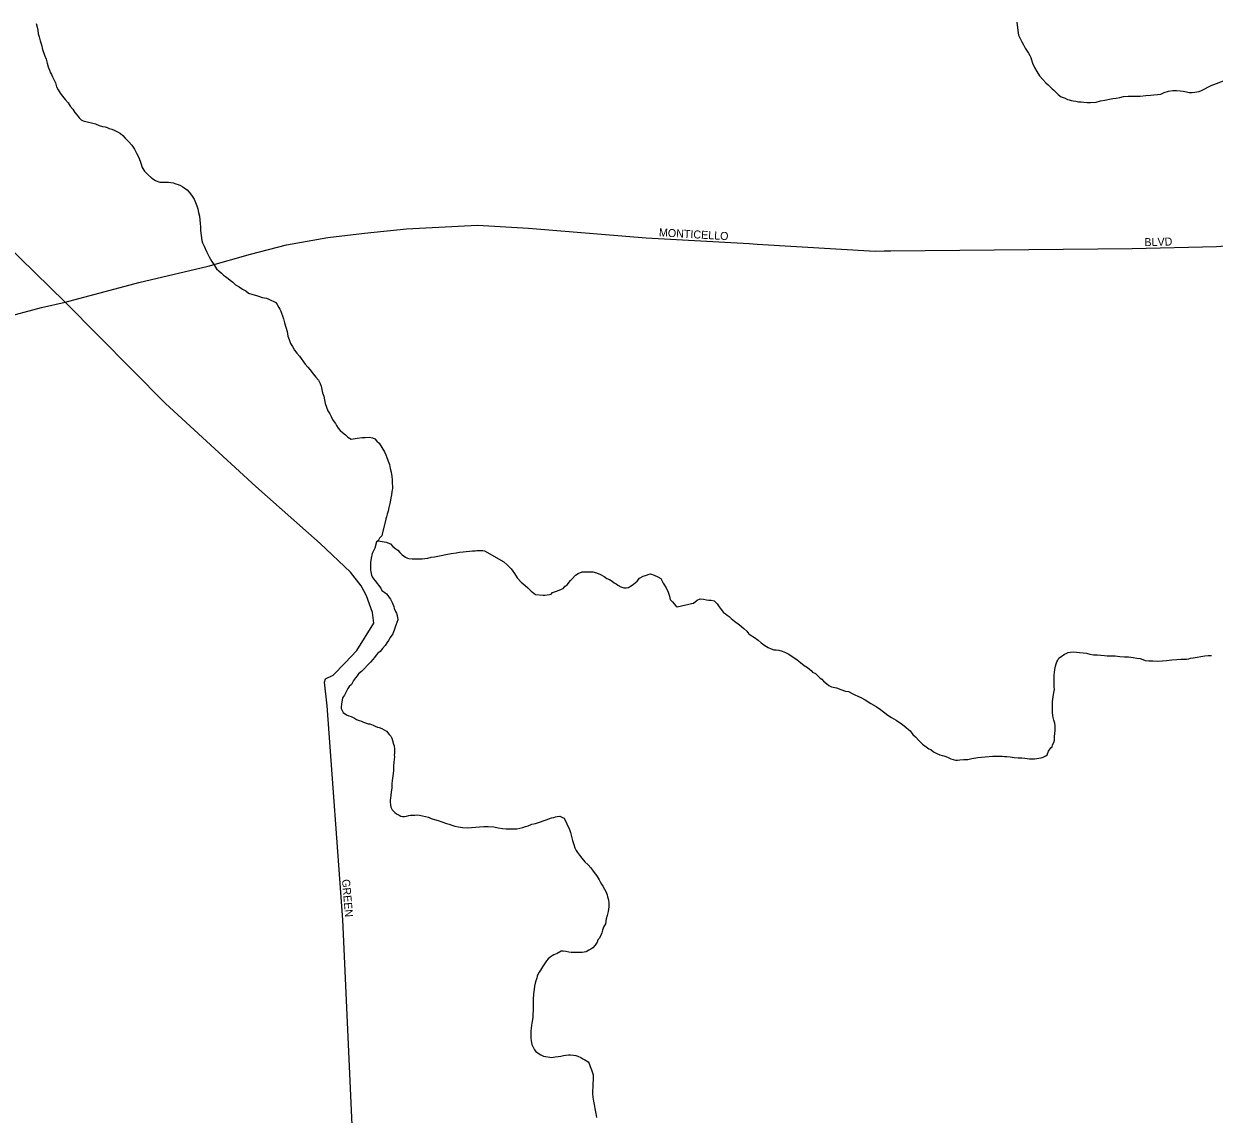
# Model space of a CAD drawing. Extents: x 2139079 to 2262683, y 1235796 to 1334992.
# Drawn here: x 2235020 to 2242458, y 1285350 to 1292167 of the extents above; entities that cross this region are included whole.
import ezdxf

# ---------------------------------------------------------------- set-up
doc = ezdxf.new("R2010")
doc.units = 0
for name, color, linetype in [('GM_X_City_Street', 7, 'Continuous'), ('GM_X_City_Street_Text', 7, 'Continuous'), ('GM_X_Minor_River', 7, 'Continuous')]:
    doc.layers.add(name, color=color, linetype=linetype)

msp = doc.modelspace()

# ---------------------------------------------------------------- linework, layer by layer
at = {"layer": 'GM_X_City_Street'}
for points in [[(2237139.1, 1283818.1), (2237013.6, 1286565.2), (2236914.8, 1287903.6), (2236898.9, 1288051.7), (2236904.4, 1288071.9), (2236952, 1288095.2), (2237028.2, 1288171.5), (2237100.3, 1288249.6), (2237206.3, 1288419), (2237198.5, 1288487), (2237161.7, 1288590.5), (2237128, 1288653.8), (2237061.6, 1288738.4), (2236872.5, 1288918.2), (2236470.3, 1289275.2), (2235905.5, 1289792.5), (2235277.5, 1290426.7), (2232535.6, 1293111.5)], [(2235277.5, 1290426.7), (2235737.5, 1290549), (2236172, 1290652.6), (2236436.7, 1290727.7), (2236661.8, 1290785.7), (2236919.3, 1290830.5), (2237149.2, 1290858.5), (2237411.2, 1290885.4), (2237855.7, 1290908.9), (2238173, 1290889.1), (2238908.5, 1290829.8), (2239552.6, 1290792.5)], [(2239552.6, 1290792.5), (2239603.3, 1290789.5), (2240338.8, 1290746.4), (2240396.7, 1290746.9)], [(2240396.7, 1290746.9), (2240437.6, 1290747.3), (2241946, 1290761.4), (2242473.5, 1290775.7), (2242651.3, 1290787.6), (2242817.4, 1290793.7), (2243007, 1290803.3), (2243195.4, 1290819.4)], [(2233595.7, 1289787), (2233739.2, 1289895.1), (2233988.7, 1290020), (2234081.8, 1290064.5), (2234168.9, 1290104.9), (2234373.1, 1290196.5), (2234636.1, 1290261.6), (2234883.1, 1290326.2), (2235130, 1290392.8), (2235277.5, 1290426.7)]]:
    msp.add_lwpolyline(points, dxfattribs=at)
at = {"layer": 'GM_X_Minor_River'}
for points in [[(2235097.1, 1292168.8), (2235103.6, 1292146.8)], [(2235103.6, 1292146.8), (2235108, 1292126.8), (2235110.4, 1292104.8), (2235114.9, 1292084.8), (2235121.4, 1292060.8), (2235129.9, 1292034.9), (2235136.5, 1292006.8), (2235149.3, 1291970.9), (2235159.8, 1291947), (2235166.4, 1291921.1), (2235172.9, 1291897.1), (2235179.4, 1291877.1), (2235185.7, 1291861.1), (2235192, 1291849.2), (2235198.3, 1291835.3), (2235204.5, 1291823.3), (2235210.8, 1291811.4), (2235217.1, 1291797.5), (2235223.6, 1291773.5), (2235234.1, 1291753.6), (2235246.5, 1291733.8), (2235261, 1291713.9), (2235277.5, 1291694.2), (2235296, 1291672.4), (2235310.4, 1291652.6), (2235326.9, 1291632.8), (2235339.4, 1291613), (2235353.8, 1291595.2), (2235366.2, 1291579.4), (2235378.4, 1291567.5), (2235390.7, 1291559.7), (2235467.3, 1291541.1), (2235491.6, 1291531.6), (2235511.8, 1291525.9), (2235528, 1291522.2), (2235540.1, 1291518.4), (2235552.3, 1291512.6), (2235570.4, 1291509), (2235584.6, 1291501.2), (2235604.9, 1291491.6), (2235623.2, 1291481.9), (2235637.5, 1291468.1), (2235653.9, 1291452.3), (2235674.4, 1291430.6), (2235694.9, 1291408.9), (2235711.5, 1291383.1), (2235724.1, 1291357.3), (2235738.7, 1291331.4), (2235751.5, 1291295.5), (2235760, 1291269.6), (2235774.6, 1291245.7), (2235795.1, 1291224), (2235819.6, 1291202.4), (2235842, 1291186.8), (2235856.2, 1291181), (2235870.3, 1291177.3), (2235898.4, 1291177.8), (2235924.6, 1291176.3), (2235952.8, 1291172.8), (2235969, 1291167.1), (2235985.1, 1291161.4), (2235999.3, 1291155.6), (2236013.5, 1291147.9), (2236029.8, 1291136.1), (2236040, 1291128.3), (2236052.4, 1291114.5), (2236066.8, 1291094.7), (2236083.4, 1291070.9), (2236091.8, 1291048.9), (2236100.3, 1291029), (2236106.7, 1291011.1), (2236111.2, 1290987.1), (2236117.7, 1290965.1), (2236120.2, 1290941), (2236122.6, 1290919), (2236123.1, 1290896.9), (2236123.5, 1290874.8), (2236132.8, 1290812.7), (2236137.1, 1290798.7), (2236141.3, 1290788.8), (2236147.6, 1290776.8), (2236153.9, 1290762.9), (2236162.4, 1290738.9), (2236177, 1290711.1), (2236193.7, 1290681.3), (2236210.3, 1290655.5), (2236224.8, 1290635.7), (2236239.1, 1290621.9), (2236255.5, 1290608.1), (2236267.7, 1290596.3), (2236280, 1290586.5), (2236296.3, 1290574.8), (2236308.5, 1290565), (2236324.9, 1290551.2), (2236343.3, 1290535.5), (2236365.6, 1290521.9), (2236386, 1290508.2), (2236406.3, 1290496.6), (2236424.7, 1290482.8), (2236450.9, 1290475.3), (2236473.2, 1290467.7)], [(2241225.6, 1292176.8), (2241230.7, 1292124.7), (2241235.2, 1292096.6), (2241245.7, 1292074.7), (2241256.2, 1292054.8), (2241266.6, 1292035), (2241277.1, 1292015.1), (2241289.5, 1291995.2), (2241297.8, 1291983.3), (2241306.1, 1291969.4), (2241312.4, 1291955.5), (2241316.7, 1291941.5), (2241323.2, 1291921.6), (2241335.8, 1291893.7), (2241350.3, 1291869.8), (2241366.9, 1291842), (2241387.5, 1291818.3), (2241406, 1291798.6), (2241420.3, 1291784.8), (2241432.6, 1291773), (2241444.9, 1291761.2), (2241457.1, 1291751.4), (2241467.4, 1291741.5), (2241483.8, 1291725.8), (2241502.2, 1291710.1), (2241526.4, 1291702.5), (2241540.6, 1291694.7)], [(2242438.3, 1291781.6), (2242550.5, 1291823.1)], [(2241540.6, 1291694.7), (2241552.8, 1291690.9), (2241564.9, 1291687.2), (2241577, 1291685.4), (2241593.1, 1291683.7), (2241611.2, 1291680), (2241627.3, 1291678.3), (2241643.4, 1291676.6), (2241663.5, 1291675), (2241685.6, 1291675.4), (2241719.7, 1291678.1), (2241747.7, 1291684.7), (2241775.7, 1291689.2), (2241803.7, 1291695.8), (2241825.7, 1291700.2), (2241845.7, 1291702.6), (2241867.7, 1291707.1), (2241891.7, 1291711.6), (2241919.8, 1291714.1), (2241945.9, 1291714.6), (2241972, 1291715.1), (2241996, 1291715.6), (2242030.1, 1291718.3), (2242060.2, 1291720.8), (2242124.3, 1291728.1), (2242146.2, 1291736.6), (2242172.2, 1291745.1), (2242200.2, 1291749.7), (2242222.2, 1291750.1), (2242246.4, 1291748.6), (2242264.5, 1291744.9), (2242284.7, 1291741.3), (2242300.8, 1291737.6), (2242320.9, 1291737.9), (2242336.9, 1291740.3), (2242348.9, 1291742.5), (2242364.9, 1291744.8), (2242378.9, 1291751.1), (2242438.3, 1291781.6)], [(2236473.2, 1290467.7), (2236493.4, 1290462.1), (2236509.6, 1290456.4), (2236523.7, 1290454.6), (2236535.8, 1290450.8), (2236550, 1290445.1), (2236564.1, 1290439.3), (2236582.4, 1290431.7), (2236594.6, 1290423.9), (2236602.8, 1290412), (2236613.2, 1290394.1), (2236619.5, 1290382.2), (2236625.8, 1290370.2), (2236630, 1290358.2), (2236636.4, 1290342.3), (2236642.8, 1290322.3), (2236649.3, 1290298.4), (2236657.9, 1290270.4), (2236664.5, 1290242.4), (2236669.1, 1290214.4), (2236677.6, 1290192.4), (2236686.1, 1290168.5), (2236698.6, 1290148.6), (2236711.1, 1290126.8), (2236725.5, 1290107), (2236742, 1290089.2), (2236777.1, 1290039.7), (2236793.6, 1290019.9), (2236807.9, 1290006.1), (2236828.6, 1289978.4), (2236845, 1289958.6), (2236861.5, 1289938.9), (2236871.9, 1289919), (2236878.3, 1289901), (2236882.7, 1289881), (2236887.2, 1289859), (2236893.6, 1289839), (2236898.1, 1289817), (2236902.6, 1289793), (2236911.1, 1289771.1), (2236919.6, 1289747.1), (2236932, 1289729.3), (2236940.4, 1289711.4), (2236948.8, 1289693.4), (2236959.2, 1289677.6), (2236967.4, 1289667.7), (2236973.7, 1289655.8), (2236984, 1289639.9), (2236996.4, 1289624.1), (2237010.7, 1289612.3), (2237029.1, 1289596.6), (2237045.5, 1289582.8), (2237065.8, 1289571.2), (2237101.8, 1289575.9), (2237133.9, 1289580.5), (2237151.9, 1289580.9), (2237180, 1289583.4), (2237198.2, 1289577.8), (2237212.4, 1289572), (2237226.7, 1289558.2), (2237241, 1289544.4), (2237274.2, 1289490.8), (2237282.6, 1289472.9), (2237289, 1289454.9), (2237295.5, 1289433), (2237304, 1289411.1), (2237308.5, 1289387), (2237315, 1289363.1), (2237319.6, 1289337), (2237322, 1289315), (2237322.4, 1289294.9), (2237322.8, 1289274.8), (2237323.1, 1289262.8), (2237321.3, 1289252.7), (2237319.5, 1289240.6), (2237317.9, 1289222.5), (2237314.2, 1289204.3), (2237310.5, 1289188.2), (2237306.9, 1289168), (2237301.4, 1289143.8), (2237295.9, 1289119.6), (2237290.2, 1289101.4), (2237286.5, 1289085.3), (2237282.8, 1289073.2), (2237281.3, 1289069.4)], [(2237281.3, 1289069.4), (2237258.6, 1288976.3), (2237256.8, 1288966.2), (2237243.1, 1288951.8), (2237233.4, 1288935.6), (2237223.4, 1288929.4), (2237212.2, 1288889), (2237196.9, 1288854.5), (2237189.4, 1288826.3), (2237185.9, 1288800.1), (2237186.2, 1288784), (2237186.5, 1288770), (2237186.9, 1288753.9), (2237189.2, 1288739.9), (2237189.4, 1288729.8), (2237191.6, 1288719.8), (2237195.8, 1288709.9), (2237204.1, 1288698), (2237214.4, 1288684.1), (2237251.5, 1288638.6), (2237257.8, 1288624.7), (2237276.1, 1288611), (2237286.3, 1288603.2), (2237294.6, 1288593.3), (2237302.8, 1288581.4), (2237311.1, 1288569.5), (2237321.6, 1288549.6), (2237325.8, 1288539.6), (2237332.1, 1288523.7), (2237334.4, 1288511.7), (2237342.8, 1288493.8), (2237349, 1288481.8), (2237353.3, 1288467.8), (2237355.9, 1288439.8), (2237344.5, 1288407.4), (2237338.9, 1288389.2), (2237325.6, 1288352.8), (2237310, 1288330.4), (2237298.3, 1288312.1), (2237288.5, 1288297.9), (2237276.9, 1288279.6), (2237261.2, 1288261.2), (2237245.5, 1288242.8), (2237231.6, 1288232.5), (2237221.8, 1288220.2), (2237212.1, 1288206), (2237200.3, 1288193.7), (2237186.6, 1288175.4), (2237129.5, 1288118), (2237111.8, 1288103.6), (2237102, 1288091.4), (2237092.2, 1288079.1), (2237080.5, 1288060.8), (2237066.9, 1288036.4), (2237053.1, 1288024.1), (2237045.4, 1288011.9), (2237024.1, 1287969.3), (2237010.4, 1287953), (2237005.2, 1287912.7), (2237003.5, 1287896.6), (2237003.7, 1287886.6), (2237016.3, 1287860.7), (2237036.7, 1287847), (2237050.8, 1287841.3), (2237065, 1287835.5), (2237085.3, 1287825.9), (2237099.5, 1287818.1), (2237115.7, 1287812.4), (2237129.9, 1287806.7), (2237142, 1287800.9), (2237154.2, 1287797.1), (2237172.3, 1287791.4), (2237182.4, 1287789.6), (2237192.6, 1287785.8), (2237202.7, 1287781.9), (2237214.8, 1287776.2), (2237229, 1287770.4), (2237241.1, 1287766.6), (2237257.3, 1287760.9), (2237285.7, 1287745.4), (2237302.2, 1287723.6), (2237312.5, 1287713.8), (2237318.8, 1287701.8), (2237323.1, 1287685.8), (2237329.6, 1287663.9), (2237333.8, 1287653.9), (2237336.3, 1287631.9), (2237336.5, 1287617.8), (2237336.7, 1287607.8), (2237335, 1287595.7), (2237335.2, 1287583.6), (2237333.5, 1287567.5), (2237331.9, 1287551.4), (2237330.3, 1287527.3), (2237329, 1287497.1), (2237325.6, 1287464.9), (2237322.2, 1287436.7), (2237318.6, 1287414.6), (2237319.1, 1287390.5), (2237315.6, 1287364.3), (2237314, 1287344.2)], [(2237233.4, 1288935.6), (2237283.7, 1288926.5), (2237310.1, 1288915), (2237326.5, 1288899.2), (2237344.8, 1288885.5), (2237357.1, 1288875.7), (2237369.4, 1288861.9), (2237383.8, 1288846.1), (2237404.1, 1288832.4), (2237416.3, 1288826.6), (2237426.4, 1288824.8), (2237446.5, 1288821.2), (2237464.6, 1288821.6), (2237474.6, 1288821.7), (2237490.7, 1288822.1), (2237508.8, 1288822.4), (2237524.8, 1288824.7), (2237544.8, 1288827.1), (2237564.8, 1288831.5), (2237586.8, 1288834), (2237606.8, 1288838.4), (2237626.8, 1288842.8), (2237656.8, 1288849.4), (2237690.8, 1288856.1), (2237720.8, 1288860.6), (2237742.9, 1288863.1), (2237764.9, 1288865.5), (2237782.9, 1288867.9), (2237805, 1288870.3), (2237823, 1288872.7), (2237839.1, 1288873), (2237851.1, 1288873.2), (2237865.2, 1288873.5), (2237877.2, 1288873.7), (2237887.2, 1288873.9), (2237899.3, 1288872.1), (2238019.2, 1288804.1)], [(2238019.2, 1288804.1), (2238041.7, 1288782.5), (2238064.3, 1288758.8), (2238084.9, 1288731.1), (2238103.6, 1288703.3), (2238128.2, 1288675.7), (2238152.7, 1288656.1), (2238169.1, 1288640.3), (2238189.6, 1288620.6), (2238205.9, 1288606.9), (2238218.1, 1288599.1), (2238264.4, 1288594), (2238276.5, 1288594.2), (2238304.5, 1288598.7), (2238314.5, 1288600.9), (2238324.3, 1288611.2), (2238354.2, 1288621.8), (2238380.1, 1288632.3), (2238390.1, 1288636.6), (2238401.8, 1288650.8), (2238415.7, 1288659.1), (2238435.2, 1288687.6), (2238447.1, 1288697.9), (2238466.7, 1288720.4), (2238484.5, 1288730.8), (2238508.4, 1288741.3), (2238574.7, 1288740.6), (2238598.9, 1288735), (2238623.2, 1288723.4), (2238645.6, 1288711.8), (2238661.9, 1288700.1), (2238680.1, 1288692.4), (2238696.4, 1288682.7), (2238708.6, 1288672.9), (2238720.8, 1288665.1), (2238731, 1288657.2), (2238751.3, 1288647.6), (2238769.5, 1288639.9), (2238783.6, 1288640.2), (2238797.6, 1288642.4), (2238811.5, 1288650.7), (2238827.3, 1288661.1), (2238841.1, 1288673.4), (2238853, 1288681.7), (2238866.7, 1288702), (2238890.5, 1288714.5), (2238910.5, 1288720.9), (2238926.4, 1288725.3), (2238936.4, 1288727.5), (2238958.7, 1288719.9), (2238981, 1288710.3), (2239001.3, 1288698.6), (2239015.9, 1288670.8), (2239034.6, 1288641), (2239045.2, 1288613.1), (2239053.7, 1288589.1), (2239055.9, 1288579.1), (2239058.2, 1288567.1), (2239072.5, 1288553.3), (2239091.1, 1288529.6), (2239103.3, 1288521.8), (2239129.2, 1288528.3), (2239175.2, 1288539.3), (2239191.2, 1288543.6), (2239205.2, 1288545.9), (2239226.9, 1288564.4), (2239246.8, 1288572.8), (2239267, 1288569.1), (2239285.1, 1288565.5), (2239301.2, 1288563.8), (2239315.3, 1288564.1), (2239333.4, 1288560.4), (2239351.9, 1288540.7), (2239364.3, 1288522.8), (2239376.7, 1288505), (2239391.1, 1288487.2)], [(2239391.1, 1288487.2), (2239403.4, 1288477.4), (2239415.6, 1288469.6), (2239427.8, 1288461.8), (2239440.1, 1288450), (2239460.5, 1288432.3), (2239491.1, 1288408.8), (2239519.7, 1288387.2), (2239538.1, 1288369.5), (2239548.4, 1288355.6), (2239558.6, 1288347.8), (2239585.1, 1288330.2), (2239607.5, 1288314.6), (2239628, 1288296.9), (2239650.4, 1288281.3), (2239670.7, 1288267.6), (2239688.9, 1288259.9), (2239707.1, 1288254.2), (2239721.2, 1288252.5), (2239737.3, 1288250.8), (2239757.5, 1288245.2), (2239779.8, 1288235.6), (2239800.1, 1288225.9), (2239853, 1288190.8), (2239873.4, 1288173.1), (2239895.9, 1288155.4), (2239916.3, 1288141.8), (2239928.5, 1288132), (2239938.7, 1288124.1), (2239948.9, 1288114.3), (2239967.2, 1288104.6), (2239981.6, 1288090.8), (2239995.9, 1288077), (2240006.1, 1288069.2), (2240016.4, 1288057.3), (2240034.7, 1288043.6), (2240051.1, 1288029.9), (2240067.3, 1288022.2), (2240097.6, 1288014.7), (2240125.9, 1288005.2), (2240154.2, 1287995.7), (2240172.3, 1287992.1), (2240200.7, 1287978.6), (2240216.9, 1287970.8), (2240227.1, 1287965), (2240249.4, 1287955.4), (2240277.8, 1287939.9), (2240312.4, 1287918.4), (2240346.9, 1287899), (2240373.4, 1287879.4), (2240418.3, 1287844.1), (2240440.7, 1287830.5), (2240471.2, 1287813), (2240509.9, 1287785.7), (2240532.3, 1287768), (2240548.7, 1287754.3), (2240558.9, 1287746.4), (2240575.4, 1287724.7), (2240591.8, 1287708.9), (2240612.3, 1287687.2), (2240634.9, 1287663.5), (2240657.3, 1287645.9), (2240675.6, 1287634.2), (2240687.7, 1287630.4), (2240704.1, 1287614.7), (2240724.4, 1287605), (2240744.6, 1287597.4), (2240758.8, 1287593.6), (2240768.9, 1287589.8), (2240781, 1287586), (2240795.2, 1287580.3), (2240813.4, 1287572.6), (2240841.7, 1287563.1), (2240853.8, 1287563.3), (2240867.8, 1287565.6), (2240893.8, 1287568.1), (2240917.9, 1287568.6), (2240943.9, 1287573.1), (2240982, 1287579.9), (2241028, 1287584.8), (2241074.2, 1287587.7), (2241106.3, 1287588.3), (2241132.4, 1287588.8), (2241148.5, 1287587.1), (2241162.6, 1287585.4), (2241182.7, 1287583.7), (2241208.9, 1287580.2), (2241233, 1287578.7), (2241257.1, 1287577.1), (2241275.2, 1287575.5), (2241289.3, 1287573.8), (2241303.4, 1287572), (2241317.4, 1287572.3), (2241335.5, 1287572.6), (2241377.6, 1287577.5), (2241389.6, 1287581.7), (2241405.4, 1287590.1), (2241415.4, 1287596.3), (2241422.9, 1287620.5), (2241436.5, 1287640.9), (2241446.4, 1287647.1)], [(2241446.4, 1287647.1), (2241448.2, 1287659.2), (2241456, 1287673.4), (2241459.7, 1287687.5), (2241459.5, 1287697.6), (2241461.2, 1287711.7), (2241462.8, 1287729.8), (2241464.4, 1287749.9), (2241464.2, 1287761.9), (2241463.9, 1287776), (2241461.5, 1287794), (2241457.1, 1287814), (2241452.8, 1287830), (2241450.5, 1287842), (2241448.1, 1287862.1), (2241447.4, 1287896.2), (2241448.7, 1287930.4), (2241452.1, 1287958.6), (2241455.6, 1287986.8), (2241461.2, 1288004.9), (2241458.9, 1288021), (2241458.7, 1288031), (2241458.4, 1288045.1), (2241458.1, 1288059.1), (2241457.8, 1288077.2), (2241457.4, 1288095.3), (2241461.1, 1288111.4), (2241462.7, 1288129.5), (2241466.3, 1288151.7), (2241470, 1288165.8), (2241475.8, 1288178), (2241481.6, 1288188.1), (2241487.4, 1288200.3), (2241523, 1288227.1), (2241532.9, 1288231.3), (2241544.9, 1288235.6), (2241558.9, 1288237.8), (2241578.9, 1288240.2), (2241597, 1288238.6), (2241617.2, 1288237), (2241639.3, 1288235.4), (2241659.4, 1288231.8), (2241681.6, 1288226.2), (2241703.8, 1288222.6), (2241727.9, 1288221), (2241750.1, 1288219.4), (2241772.2, 1288217.9), (2241790.3, 1288216.2), (2241814.4, 1288214.7), (2241838.5, 1288215.1), (2241868.7, 1288211.7), (2241896.8, 1288210.2), (2241923, 1288208.7), (2241951.1, 1288205.3), (2241975.3, 1288201.7), (2241995.5, 1288198.1), (2242011.6, 1288192.4), (2242027.8, 1288186.6), (2242049.9, 1288185.1), (2242074.1, 1288183.5), (2242102.2, 1288182.1), (2242132.3, 1288184.7), (2242160.4, 1288187.2), (2242192.4, 1288189.8), (2242224.5, 1288192.5), (2242250.6, 1288195), (2242268.6, 1288195.3), (2242284.7, 1288195.6), (2242298.7, 1288197.9), (2242310.7, 1288200.2), (2242326.7, 1288202.5), (2242350.7, 1288207), (2242374.7, 1288211.4), (2242398.7, 1288215.9), (2242420.8, 1288218.4), (2242434.8, 1288218.6), (2242436.8, 1288218.7), (2242440.9, 1288216.8)], [(2237314, 1287344.2), (2237310.4, 1287326), (2237308.6, 1287313.9), (2237308.9, 1287299.9), (2237311.2, 1287283.9), (2237313.5, 1287269.8), (2237321.9, 1287253.9), (2237338.3, 1287236.2), (2237348.5, 1287228.3), (2237364.8, 1287218.6), (2237374.9, 1287212.8), (2237387, 1287211), (2237399, 1287211.2), (2237411, 1287213.5), (2237425, 1287217.8), (2237437, 1287220), (2237451.1, 1287220.3), (2237463.1, 1287220.5), (2237475.2, 1287220.7), (2237491.3, 1287219), (2237547.7, 1287206.1), (2237566, 1287198.4), (2237586.2, 1287192.8), (2237608.4, 1287185.2), (2237632.7, 1287177.6), (2237661, 1287168.1), (2237677.1, 1287162.4), (2237693.3, 1287156.7), (2237713.5, 1287151), (2237735.7, 1287147.4), (2237761.9, 1287141.9), (2237790.1, 1287140.5), (2237818.1, 1287143), (2237844.2, 1287145.5), (2237868.2, 1287146), (2237894.3, 1287148.5), (2237920.4, 1287149), (2237956.6, 1287145.7), (2237984.8, 1287140.2), (2238011, 1287136.7), (2238033.2, 1287133.1), (2238057.3, 1287133.6), (2238083.4, 1287134.1), (2238101.4, 1287134.4), (2238119.4, 1287138.8), (2238137.4, 1287143.2), (2238155.3, 1287149.5), (2238171.3, 1287153.8), (2238195.2, 1287162.4), (2238217.2, 1287166.8), (2238235.2, 1287173.2), (2238249.1, 1287177.5), (2238265.1, 1287183.8), (2238283, 1287190.2), (2238301, 1287196.5), (2238316.9, 1287202.9), (2238330.9, 1287205.2), (2238342.9, 1287209.4), (2238352.9, 1287211.6), (2238368.9, 1287213.9), (2238385.1, 1287204.2), (2238395.3, 1287200.4), (2238428.8, 1287130.7), (2238435.2, 1287110.8), (2238441.8, 1287086.8), (2238448.3, 1287060.8), (2238456.8, 1287036.8), (2238463.3, 1287014.9), (2238471.7, 1286999), (2238480, 1286985.1), (2238492.4, 1286969.2), (2238506.8, 1286951.4), (2238525.3, 1286927.7), (2238545.8, 1286910), (2238562.2, 1286890.2), (2238576.7, 1286868.4), (2238591.2, 1286850.6), (2238601.5, 1286836.8), (2238609.7, 1286824.9), (2238616, 1286814.9), (2238622.2, 1286803), (2238630.6, 1286789.1), (2238638.9, 1286775.2), (2238647.3, 1286757.3), (2238655.6, 1286741.4), (2238659.8, 1286731.4), (2238664.1, 1286721.5), (2238666.3, 1286709.4), (2238670.6, 1286697.5), (2238672.8, 1286685.5), (2238675.1, 1286673.5), (2238675.6, 1286647.4), (2238670.2, 1286617.1), (2238664.7, 1286592.9), (2238659.1, 1286570.7), (2238653.7, 1286540.5), (2238642.1, 1286520.1), (2238636.5, 1286500), (2238630.8, 1286483.8), (2238623.1, 1286463.6), (2238615.4, 1286449.3)], [(2238615.4, 1286449.3), (2238607.6, 1286439.1), (2238601.8, 1286425), (2238590.2, 1286406.7), (2238574.4, 1286390.3), (2238562.6, 1286382), (2238550.6, 1286375.8), (2238532.8, 1286365.4), (2238520.8, 1286363.1), (2238508.8, 1286360.9), (2238498.7, 1286360.7), (2238486.7, 1286360.5), (2238440.5, 1286361.6), (2238426.4, 1286363.3), (2238406.2, 1286366.9), (2238390.1, 1286368.6), (2238378.1, 1286368.4), (2238352.3, 1286353.8), (2238332.3, 1286347.4), (2238320.5, 1286339.2), (2238308.6, 1286330.9), (2238296.7, 1286320.6), (2238284.9, 1286308.4), (2238273.3, 1286290.1), (2238261.6, 1286271.7), (2238247.9, 1286251.4), (2238240.2, 1286237.2), (2238232.5, 1286223), (2238228.6, 1286212.8), (2238224.9, 1286200.7), (2238219.2, 1286184.5), (2238215.5, 1286168.4), (2238211.9, 1286150.3), (2238208.2, 1286132.1), (2238204.8, 1286101.9), (2238203.5, 1286067.7), (2238202.2, 1286033.6), (2238202.6, 1286011.5), (2238203, 1285995.4), (2238201.3, 1285977.3), (2238199.8, 1285955.2), (2238196.2, 1285931), (2238192.7, 1285906.8), (2238189.1, 1285886.7), (2238187.4, 1285872.6), (2238187.6, 1285860.5), (2238188, 1285844.5), (2238188.3, 1285826.4), (2238190.7, 1285808.3), (2238195.2, 1285786.3), (2238199.5, 1285772.4), (2238211.9, 1285752.5), (2238220.2, 1285742.6), (2238234.5, 1285730.9), (2238250.7, 1285721.1), (2238266.9, 1285713.4), (2238319.3, 1285704.4), (2238339.3, 1285708.8), (2238359.4, 1285711.2), (2238375.4, 1285713.5), (2238391.4, 1285717.8), (2238407.4, 1285720.1), (2238423.4, 1285720.4), (2238435.5, 1285720.7), (2238453.6, 1285719), (2238469.7, 1285717.3), (2238481.8, 1285713.6), (2238500.1, 1285703.9), (2238512.3, 1285696.1), (2238524.5, 1285690.3), (2238536.6, 1285684.5), (2238546.8, 1285676.6), (2238553, 1285666.7), (2238559.4, 1285648.8), (2238567.9, 1285626.8), (2238572.3, 1285608.8), (2238576.5, 1285596.9), (2238576.9, 1285580.8), (2238577.2, 1285564.7), (2238575.7, 1285542.6), (2238576.1, 1285518.5), (2238572.5, 1285498.4), (2238572.9, 1285478.3), (2238575.4, 1285456.2), (2238579.9, 1285432.2), (2238584.4, 1285410.2), (2238588.9, 1285386.2), (2238593.6, 1285354.1), (2238598.1, 1285330.1)]]:
    msp.add_lwpolyline(points, dxfattribs=at)

# ---------------------------------------------------------------- texts
at = {"layer": 'GM_X_City_Street_Text'}
for s, rotation, p in [('MONTICELLO', 356.8195, (2238987.4, 1290838.4)), ('BLVD', 1.50653, (2242022.7, 1290776.8)), ('GREEN', 274.96688, (2237007.5, 1286817.1))]:
    msp.add_text(s, height=50, rotation=rotation, dxfattribs=at).set_placement(p)

doc.saveas('drawing.dxf')
